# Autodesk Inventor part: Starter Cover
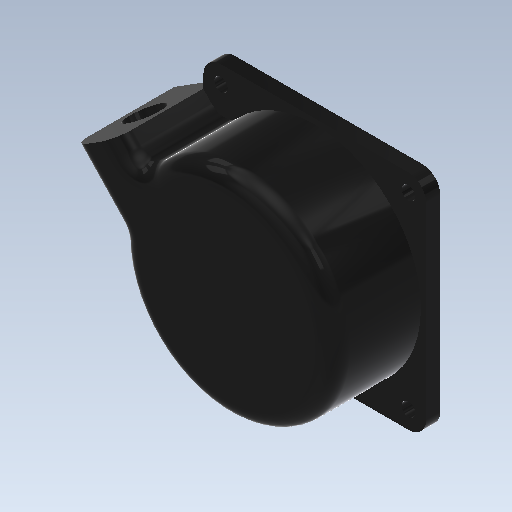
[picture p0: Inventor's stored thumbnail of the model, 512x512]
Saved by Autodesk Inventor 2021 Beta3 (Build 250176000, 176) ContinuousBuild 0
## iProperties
Created: 2012-08
Part Number: Starter Cover
Material: PC/ABS Plastic
Document SubType Name: Modeling
Designer: John
Mass: 10.273 g
Surface Area: 76.886 cm^2
Volume: 6.88076 cm^3
Density: 1.493 g/cm^3
Appearance: Smooth - Black
Author: John
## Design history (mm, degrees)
sketch "Sketch1"
  geometry: L1 (16.827, -20.002)-(-16.827, -20.002) reference; L2 (20.002, 16.827)-(20.002, -16.827) reference; L3 (-16.827, 20.002)-(16.827, 20.002) reference; L4 (-20.002, -16.827)-(-20.002, 1.537) reference; L5 (-20.002, 14.618)-(-20.002, 16.827) reference; L6 (-20.002, 14.618)-(-27.749, 9.741) reference; L7 (-27.749, 9.741)-(-20.002, 1.537) reference; C1 r 10.477 at (0, 0) reference; C2 r 1.016 at (9.093, -9.093) reference; C3 r 1.016 at (9.093, 9.093) reference; C4 r 1.016 at (-9.093, 9.093) reference; C5 r 1.016 at (-9.093, -9.093) reference; C6 r 1.079 at (16.827, -16.827) reference; C7 r 1.079 at (-16.827, 16.827) reference; C8 r 1.079 at (-16.827, -16.827) reference; C9 r 1.079 at (16.827, 16.827) reference; A1 r 3.175 centre (-16.827, -16.827) between (-20.002, -16.827) and (-16.827, -20.002) reference; A2 r 3.175 centre (16.827, -16.827) between (16.827, -20.002) and (20.002, -16.827) reference; A3 r 3.175 centre (16.827, 16.827) between (20.002, 16.827) and (16.827, 20.002) reference; A4 r 3.175 centre (-16.827, 16.827) between (-16.827, 20.002) and (-20.002, 16.827) reference; 1 further point
extrude "Extrusion1" new body sketch "Sketch1" distance "d0" = 2.54; taper "d1" = 0 deg
sketch "Sketch2"
  geometry: L1 (-27.749, 9.741)-(-20.002, 1.537) reference; L2 (-20.002, 1.537)-(-19.043, 0.52); L3 (-20.002, 14.618)-(-15.985, 10.363); L4 (-20.002, 14.618)-(-27.749, 9.741) reference; L5 (-20.002, 14.618)-(-27.749, 9.741); L6 (-27.749, 9.741)-(-20.002, 1.537); A1 r 19.05 centre (0, 0) between (-19.043, 0.52) and (-15.985, 10.363); 1 further point
  constraints: 8 end point, 3 collinear, 2 point on circle, 1 centre point, 1 coincident, 1 parallel
  dimensions: "d2" = 38.1 diameter of A1
extrude "Extrusion2" join sketch "Sketch2" distance "d4" = 15.875; taper "d5" = 0 deg
fillet "Fillet4" dims "d42" = 3.175
fillet "Fillet3" dims "d19" = 3.175
shell "Shell4" dims "d44" = 1.905
sketch "Sketch10"
  geometry: L1 (-9.154, 2.54)-(0, 2.54) reference; L2 (-3.236, -15.875)-(-5.918, -15.875) reference; L3 (-4.577, 2.54)-(-4.577, -15.875); 2 further points
  constraints: 3 midpoint, 2 end point
hole "Hole3" sketch "Sketch10" at (-4.577, -6.667) diameter "d45" = 2.54; stored, may be unused: countersink angle "d49" = 82 deg, drill point angle "d51" = 118 deg; dims "d46" = 19.05, "d47" = 6.35, "d48" = 1.5875, "d50" = 25.4
sketch "Sketch11"
  geometry: C1 r 1.079 at (16.827, -16.827) reference; C2 r 1.079 at (-16.827, 16.827) reference; C3 r 1.079 at (-16.827, -16.827) reference; C4 r 1.079 at (16.827, 16.827) reference
hole "Hole4" sketch "Sketch11" at (-16.827, 16.827), (16.827, 16.827), (-16.827, -16.827), (16.827, -16.827) diameter "d52" = 2.4384; stored, may be unused: countersink angle "d56" = 82 deg, drill point angle "d58" = 118 deg; dims "d53" = 19.05, "d54" = 4.3688, "d55" = 6.35, "d57" = 25.4
body "Solid1"
node "Reference1"
